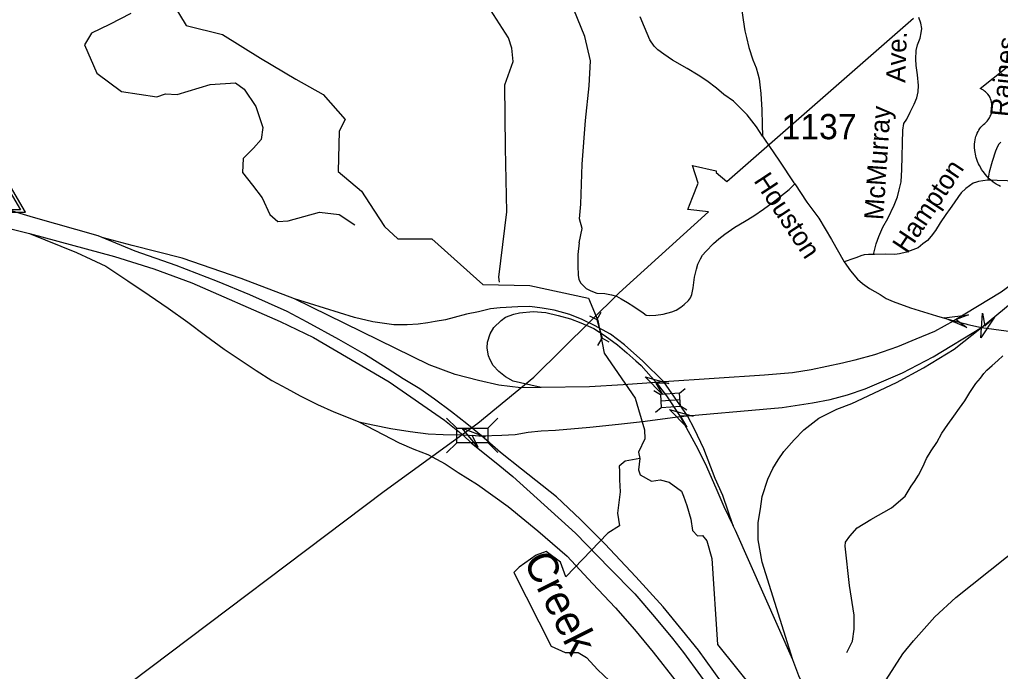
# Model space of a CAD drawing. Extents: x 990631 to 1056237, y 535999 to 585651.
# Drawn here: x 1039191 to 1044054, y 560525 to 563754 of the extents above; entities that cross this region are included whole.
import ezdxf

# ---------------------------------------------------------------- set-up
doc = ezdxf.new("R2010")
doc.units = 0
for name, color, linetype in [('Exist Boundary Political City Limit New', 7, 'Continuous'), ('Exist Hydrographic Creek Single Shore', 7, 'Continuous'), ('Exist Hydrographic Creek Single Shore Label', 7, 'Continuous'), ('Exist Road Non-System Type 51', 7, 'Continuous'), ('Exist Road Non-System Type 51 Label', 7, 'Continuous'), ('Exist Road Primary Interstate Divided Center Attributed', 7, 'Continuous'), ('Exist Road Primary Interstate Ramp 1 Lane Attributed', 7, 'Continuous'), ('Exist Road Primary Interstate Structure Standard Bridge CELL', 7, 'Continuous'), ('Exist Road Primary NC Attributed', 7, 'Continuous'), ('Exist Road Primary US Divided Attributed', 7, 'Continuous'), ('Exist Road Primary US Shield CELL', 7, 'Continuous'), ('Exist Road Secondary Structure Culvert CELL', 7, 'Continuous'), ('Exist Road Secondary Structure Standard Bridge Attributed CELL', 7, 'Continuous'), ('Exist Road Secondary Type 51 Attributed', 7, 'Continuous'), ('Exist Road Secondary Type 51 Label', 7, 'Continuous'), ('Exist Road Secondary Type 51 Number Label', 7, 'Continuous'), ('Exist Survey Geodetic Marker CELL', 7, 'Continuous')]:
    doc.layers.add(name, color=color, linetype=linetype)

msp = doc.modelspace()

# ---------------------------------------------------------------- linework, layer by layer
at = {"layer": 'Exist Boundary Political City Limit New'}
msp.add_lwpolyline([(1040073.9, 557988.5), (1039959.6, 558234.4), (1040030.1, 558256.9), (1039357.1, 559263.7), (1038967.6, 559887.1), (1039740.5, 560469.5), (1040999.5, 561417.5), (1041463.6, 561753.6), (1041741.1, 561981.8), (1042163.9, 562399.8), (1042607.6, 562801.8), (1042504.3, 562813.3), (1042528.4, 562873.1), (1042556.6, 562942.8), (1042527.6, 563031.9), (1042644.9, 563004.8), (1042645.8, 562995.9), (1042698.7, 562951.6), (1043624.2, 563761.7)], dxfattribs=at)
at = {"layer": 'Exist Hydrographic Creek Single Shore'}
for points in [[(1039816.1, 563950.7), (1039917.4, 563890.2), (1040017, 563724.5), (1040198.1, 563679.6), (1040385.2, 563562.6), (1040560.2, 563458.8), (1040697.1, 563383.2), (1040806.2, 563258.4), (1040776.4, 563201), (1040771.3, 563000.9), (1040886.3, 562903.4), (1040926.2, 562843.5), (1041000.9, 562729.6), (1041067.1, 562667.1), (1041234.8, 562667.1), (1041488.8, 562441.6), (1041720.9, 562435.8), (1042012.7, 562374.3), (1042058.8, 562262.9), (1042089.5, 562101.5), (1042243.1, 561878.7)], [(1041571.4, 562452.3), (1041567.3, 562478), (1041607.8, 562802.3), (1041601.2, 563118), (1041597.5, 563430.3), (1041638.7, 563546.9), (1041631.8, 563612.1), (1041614.6, 563663.6), (1041422.6, 563965.5)], [(1042243.1, 561878.7), (1042290.4, 561722)], [(1042290.4, 561722), (1042291.5, 561676), (1042260.1, 561610.8), (1042266.8, 561578.8), (1042193.8, 561565.3), (1042163.4, 561540.6), (1042165.7, 561515.8), (1042165.7, 561473.1), (1042169.1, 561413.6), (1042156.7, 561309.1), (1042165.7, 561245), (1042108.4, 561209.6), (1041899.4, 560992.8), (1041873.5, 561066.4), (1041802.7, 561119.2), (1041753.3, 561100.1), (1041667.9, 561041.6), (1041642.1, 561013.6), (1041826.3, 560648.9), (1041896, 560617.5), (1041960.1, 560617.5), (1042002.8, 560592.7), (1042058.9, 560532.1), (1042114, 560479.3)], [(1042266.8, 561578.8), (1042260.1, 561522.6), (1042269.1, 561499), (1042325.2, 561467.5), (1042367.9, 561474.3), (1042411.8, 561461.9), (1042473.6, 561418.1), (1042482.6, 561393.4), (1042500.5, 561346.2), (1042519.6, 561278.7), (1042528.6, 561222.6), (1042553.3, 561195.6), (1042576.9, 561197.8), (1042599.4, 561170.9), (1042624.3, 561083), (1042651, 560657.4), (1042834.2, 560432.1), (1042971.6, 560209.7), (1043109, 560049.3), (1043414.4, 560008), (1043506, 559824.7), (1043582.4, 559469.5), (1043607.2, 559178)]]:
    msp.add_lwpolyline(points, dxfattribs=at)
at = {"layer": 'Exist Road Non-System Type 51'}
for points in [[(1041965.5, 562647.8), (1041980.4, 562719.1), (1041966.7, 562767.1), (1041973.6, 562839.1), (1041980.4, 563038.2), (1041997.6, 563254.3), (1042014.7, 563425.9), (1042021.6, 563549.4), (1041994.1, 563669.5), (1041939.3, 563804.4), (1041874.1, 564003.4), (1041836.4, 564209.3), (1041819.2, 564384.3), (1041791.8, 564494.1), (1041748.5, 564614.1)], [(1039742.5, 563784.2), (1039637.3, 563729.6), (1039547.6, 563686.7), (1039512.5, 563628.2), (1039574.9, 563487.8), (1039695.7, 563398.1), (1039871.1, 563370.8), (1039914, 563386.4), (1039972.5, 563382.5), (1040136.2, 563433.2), (1040261, 563441), (1040303.9, 563409.8), (1040362.3, 563324), (1040397.4, 563218.7), (1040389.6, 563160.2), (1040350.6, 563117.3), (1040300, 563066.5), (1040296.1, 562996.3), (1040346.7, 562933.9), (1040393.5, 562871.5), (1040432.5, 562788.1), (1040471.5, 562753), (1040522.1, 562756.9), (1040678.1, 562799.8), (1040775.5, 562788.1), (1040853.5, 562737.4)], [(1043424.6, 562590.8), (1043438.3, 562642.6), (1043451.6, 562680.1), (1043470.9, 562725.5), (1043496.4, 562768.6), (1043528.5, 562833.8), (1043543.8, 562875.3), (1043553.1, 562911), (1043562.3, 562950.8), (1043566.3, 563010.7), (1043570.5, 563206.7), (1043575.5, 563238.4), (1043590.1, 563260.1), (1043607.5, 563295.6), (1043626.7, 563335), (1043639.7, 563366.6), (1043646.7, 563396.3), (1043647.7, 563428.3), (1043643.4, 563480.6), (1043636.7, 563526.7), (1043635.8, 563558.7), (1043637.2, 563600.7), (1043644.2, 563628.6), (1043657.2, 563662.1), (1043662, 563688.1), (1043664.8, 563710), (1043659.5, 563736.1), (1043650.5, 563764.5)], [(1044056.8, 563147.1), (1044046.6, 563137.3), (1044040.2, 563125.4), (1044029.5, 563101.9), (1044013.9, 563050.3), (1043998.2, 562998.8), (1043992.8, 562958.9)], [(1041965.5, 562647.8), (1041959.7, 562589.9), (1041960, 562535.8), (1041960.4, 562485.8), (1041963.9, 562467.7), (1041973.1, 562449.3), (1042000.4, 562422.4), (1042023.9, 562409.7), (1042053.7, 562398.7), (1042093.7, 562397.5), (1042125.4, 562390.4), (1042151.2, 562383.5), (1042174.8, 562370.8), (1042206.2, 562351.8), (1042237.6, 562332.8), (1042282.6, 562301.3), (1042298.2, 562288.7), (1042316.2, 562288.2), (1042346.4, 562289.2), (1042382.5, 562294), (1042425, 562306.8), (1042447.1, 562314), (1042469.6, 562329.3), (1042486.1, 562342.8), (1042508.7, 562362.1), (1042517.2, 562375.8), (1042523.7, 562391.6), (1042530.8, 562425.5), (1042538.4, 562477.2), (1042547.6, 562517), (1042554.6, 562542.7), (1042567.5, 562568.4), (1042578, 562586), (1042594.6, 562605.5), (1042631.8, 562644.4), (1042658.7, 562667.4), (1042687.4, 562690.7), (1042738.5, 562725.1), (1042785.5, 562753.5), (1042832.5, 562782), (1042879.5, 562814.5), (1042936.8, 562856.7), (1042984.2, 562893.2), (1043006.8, 562912.5), (1043035.5, 562939.6)], [(1043992.8, 562958.9), (1043966.7, 562955.9), (1043946.7, 562952.5), (1043936.4, 562948.7), (1043920.3, 562943.2), (1043901.8, 562929.8), (1043883.3, 562916.3), (1043860.7, 562895.2), (1043846.1, 562877.7), (1043825.1, 562846.3), (1043806.1, 562818.8), (1043783.3, 562787.5), (1043755.9, 562746.4), (1043732.7, 562709.1), (1043711.7, 562681.7), (1043693.1, 562660.2), (1043670.6, 562643.1), (1043646, 562623.8), (1043619.5, 562612.7), (1043589.1, 562601.7), (1043554.9, 562592.8), (1043530.6, 562589.5), (1043482.6, 562591.1), (1043430.6, 562590.7), (1043424.6, 562590.8)], [(1044144.6, 562946.1), (1044128.7, 562950.6), (1044088.8, 562955.8), (1044038.8, 562957.4), (1043992.8, 562958.9)], [(1043424.6, 562590.8), (1043400.6, 562589.7), (1043378.6, 562588.3), (1043362.4, 562582.9), (1043342.1, 562575.5), (1043328, 562570), (1043279.2, 562553.8)], [(1043293.3, 560618.8), (1043321, 560673.9), (1043329, 560733.7), (1043329.2, 560803.8), (1043305.9, 560950.7), (1043284.1, 561145.6), (1043286.9, 561165.3), (1043307.7, 561194.7), (1043345.1, 561235.6), (1043412.6, 561277.5), (1043514.3, 561334.2), (1043582.5, 561392.7), (1043612, 561442), (1043628.7, 561465.5), (1043647.7, 561496.9), (1043669.1, 561538.3), (1043688.4, 561579.7), (1043711.5, 561617.1), (1043739, 561658.1), (1043764.5, 561705.4), (1043793.8, 561748.5), (1043823.2, 561789.5), (1043852.4, 561828.7), (1043877.8, 561865.8), (1043903, 561907.1), (1043932.5, 561950.2), (1043955.3, 561977.5), (1043972.1, 562001), (1043986.7, 562016.5), (1044013.3, 562039.6), (1044042.3, 562064.8), (1044066.9, 562087.9)]]:
    msp.add_lwpolyline(points, dxfattribs=at)
at = {"layer": 'Exist Road Primary Interstate Divided Center Attributed'}
for points in [[(1039600.5, 562674), (1039581.5, 562681.8), (1039260.3, 562773.6), (1039105.6, 562819.5), (1038966.3, 562855.2), (1038859.2, 562880.8), (1038745.4, 562902.9), (1038645.1, 562914.8), (1038408, 562926.1), (1038149.5, 562961), (1037990.1, 562982.4), (1037802.6, 563003.9), (1037599, 563028), (1037373.9, 563046.7), (1037155.6, 563058.8), (1036983.1, 563069), (1036964, 563070.2), (1036848.9, 563077.1), (1036652.4, 563089.6)], [(1036616.9, 563035.1), (1037143.5, 563005.2), (1037360.5, 562986.4), (1037616.4, 562958.3), (1037911.1, 562923.5), (1038670.6, 562818.9), (1038820.6, 562792.1), (1039040.2, 562743.9), (1039239.7, 562694.9)], [(1039239.7, 562694.9), (1039661.8, 562580.4), (1039857.3, 562518.8), (1040044.9, 562449.1), (1040482.9, 562258.8), (1040649, 562178.4), (1041024, 561958.6), (1041297.3, 561769.7), (1041388.8, 561695.9)], [(1041481.9, 561691.2), (1041408.5, 561750.9), (1041332.1, 561811.2), (1041249.1, 561872.8), (1041175.4, 561923.8), (1041092.3, 561974.7), (1041013.3, 562025.6), (1040900.8, 562096.6), (1040774.9, 562169), (1040616.8, 562254.8), (1040517.7, 562307), (1040332.9, 562390.1), (1040172.1, 562455.8), (1039967.2, 562534.8), (1039763.6, 562607.2), (1039600.5, 562674)], [(1041388.8, 561695.9), (1041431.2, 561655.8), (1041554.5, 561557.9), (1041637.5, 561490.9), (1041947.6, 561209.1), (1042116.3, 561036.3), (1042242.3, 560909), (1042340, 560795.1), (1042428.4, 560687.9), (1042483.4, 560618.2), (1042567.4, 560501.8), (1042624, 560426.5), (1042753.9, 560241.6), (1042851.7, 560083.5), (1042956.2, 559903.9), (1043013.8, 559788.7), (1043055.1, 559700.3)], [(1043093.8, 559748.6), (1043070.1, 559808.8), (1043011.1, 559932.1), (1042940.1, 560064.7), (1042859.8, 560201.4), (1042788.8, 560308.6), (1042672.2, 560470.8), (1042557, 560628.9), (1042478, 560726.7), (1042381.6, 560844.6), (1042246.3, 560993.4), (1042093.6, 561156.9), (1041973, 561277.5), (1041853.8, 561388.7), (1041679.7, 561526.7), (1041575.2, 561608.5), (1041481.9, 561691.2)]]:
    msp.add_lwpolyline(points, dxfattribs=at)
at = {"layer": 'Exist Road Primary Interstate Ramp 1 Lane Attributed'}
msp.add_line((1042502.4, 561790.8), (1042385.5, 561959.5), dxfattribs=at)
for points in [[(1042385.5, 561959.5), (1042281.1, 562061.8), (1042190.4, 562141.8), (1042121.3, 562195.6), (1042041.7, 562239.1), (1041980.2, 562268.3), (1041919.1, 562292), (1041842.3, 562313.5), (1041782.3, 562324.3), (1041721.6, 562332), (1041661.6, 562331.3), (1041574.2, 562325.4), (1041526.4, 562320.8), (1041467, 562305.6), (1041407.5, 562293.9), (1041345.8, 562277.6), (1041303.8, 562267.1), (1041251.4, 562257.8), (1041215.2, 562250.8), (1041168.2, 562244.8), (1041112.2, 562241.3), (1041047, 562242.4), (1040943.2, 562256.4), (1040851.2, 562277.4), (1040553.6, 562370.6)], [(1041777.4, 561931.4), (1041674.4, 561953.4), (1041638.3, 561962.7), (1041601, 561983.7), (1041566.9, 562009.9), (1041539.7, 562040.9), (1041524.6, 562067.4), (1041515.9, 562087.5), (1041512.4, 562106.1), (1041509.5, 562127.7), (1041511.8, 562155.7), (1041524.1, 562197.1), (1041543.4, 562228.5), (1041578.8, 562263.6), (1041601.1, 562279.2), (1041641.8, 562293.9), (1041669.7, 562300.9), (1041737.3, 562307.9)], [(1041737.3, 562307.9), (1041800.3, 562302.1), (1041862, 562288.1), (1041922.6, 562270.6), (1041973.9, 562251.9), (1042039.2, 562222.8), (1042094, 562186.6), (1042155.7, 562142.3), (1042202.3, 562102.6), (1042246.2, 562063.1), (1042273, 562039.8), (1042347.7, 561956.3)], [(1043024.5, 560581.4), (1042872.6, 561066.4), (1042853.8, 561176.4), (1042853.8, 561262.3), (1042864.5, 561329.4), (1042872.6, 561391.1), (1042900.6, 561476.9), (1042926.4, 561530.2), (1042951.8, 561573.3), (1042979.9, 561613.5), (1043031.3, 561671.6), (1043080.4, 561720.8), (1043154.1, 561778.8), (1043243.4, 561823.5), (1043317.1, 561852.6), (1043538.8, 561956.6), (1043673.6, 562028.8), (1043824.8, 562120.9), (1043960.7, 562229.1)], [(1042347.7, 561956.3), (1042398.3, 561889.3), (1042467.3, 561787.5)], [(1040873.9, 561761.5), (1041072.6, 561656.1), (1041145.2, 561625.1), (1041215.5, 561599.1), (1041302.1, 561552.3), (1041366.6, 561510.2), (1041460.9, 561450.3), (1041614.4, 561342), (1041760.4, 561221), (1041906.5, 561095), (1042032, 560959.6), (1042146.6, 560839.4), (1042241, 560732.6), (1042332, 560620.3), (1042446.6, 560474.2), (1042533.1, 560341.6), (1042616.6, 560213.2), (1042687.2, 560057), (1042750.1, 559900.7), (1042881, 559530.3)], [(1042467.3, 561787.5), (1042554.5, 561627.5), (1042596.9, 561540.2), (1042649.1, 561422), (1042683.8, 561341), (1042729.6, 561245.3)], [(1042729.6, 561245.3), (1042677.6, 561396.5), (1042640.7, 561480.9), (1042583.6, 561626.7), (1042537, 561724.7), (1042502.4, 561790.8)], [(1043024.5, 560581.4), (1042740.3, 561223), (1042729.6, 561245.3)], [(1043264.1, 560006.8), (1043179.8, 560188.8), (1043099.4, 560404.7), (1043055.5, 560502.4), (1043024.5, 560581.4)]]:
    msp.add_lwpolyline(points, dxfattribs=at)
at = {"layer": 'Exist Road Primary Interstate Structure Standard Bridge CELL'}
for p, q in [((1042336.2, 561915.5), (1042368.4, 561895.8)), ((1042463.1, 561902.3), (1042492.1, 561926.3)), ((1042370.6, 561864.3), (1042465.3, 561871)), ((1042343.8, 561808.7), (1042372.8, 561832.7)), ((1042467.5, 561840), (1042499.6, 561820.3)), ((1041308.8, 561779.1), (1041358.4, 561729.5)), ((1041512.3, 561729.1), (1041562, 561778.8)), ((1041308.8, 561607.9), (1041358.4, 561657.6)), ((1041512.3, 561658.9), (1041562, 561609.2))]:
    msp.add_line(p, q, dxfattribs=at)
for points in [[(1042372.8, 561832.7), (1042467.5, 561839.4), (1042463.1, 561902.5), (1042368.4, 561895.8)], [(1041358.4, 561729.5), (1041512.3, 561729.5), (1041512.3, 561657.6), (1041358.4, 561657.6)]]:
    msp.add_lwpolyline(points, close=True, dxfattribs=at)
at = {"layer": 'Exist Road Primary NC Attributed'}
msp.add_lwpolyline([(1043264.1, 560006.8), (1043301.1, 560087.7), (1043356.2, 560202.3), (1043396.6, 560300.1), (1043465.9, 560437.4), (1043488.5, 560482.8), (1043571.2, 560612), (1043623.3, 560676.2), (1043729.6, 560794.1), (1043834.2, 560890.3), (1044336.7, 561290.9), (1044875.9, 561701)], dxfattribs=at)
at = {"layer": 'Exist Road Primary US Divided Attributed'}
for points in [[(1045749.4, 563870.6), (1045521.5, 563680.7), (1045342.9, 563519.8), (1045208.9, 563394.6), (1044818, 563039.3), (1044797.9, 563023.6), (1044322.5, 562611.4), (1044182.1, 562494), (1044059, 562403.5), (1043823.6, 562261.7)], [(1043960.7, 562229.1), (1044274.8, 562488.4), (1044585.7, 562757.7), (1044907.3, 563037.1), (1045271.4, 563341), (1045289.3, 563358.9), (1045548.3, 563582.4), (1045803, 563790.2)], [(1039239.7, 562694.9), (1039473, 562600.2), (1039544.1, 562567.3), (1039618.4, 562532.9), (1039679, 562492.8), (1039728.1, 562459.2), (1039833.7, 562387.9), (1039927.9, 562324.8), (1040025.7, 562255.6), (1040113.6, 562188.8), (1040205.5, 562121.7), (1040289.8, 562065), (1040364.2, 562014.5), (1040442.7, 561966.1), (1040515.5, 561925.6), (1040582.4, 561889.5), (1040668.9, 561846.7), (1040749.8, 561810.1), (1040795.3, 561792.6), (1040873.9, 561761.5)], [(1040553.6, 562370.6), (1040290.2, 562470.9), (1039997.8, 562571.3), (1039749.7, 562634.2), (1039600.5, 562674)], [(1041777.4, 561931.4), (1041676.7, 561930), (1041568.1, 561942.1), (1041466.2, 561965.9), (1041350.6, 561994.8), (1041221.4, 562044.1), (1040553.6, 562370.6)], [(1043823.6, 562261.7), (1043727.3, 562209.1), (1043634.6, 562170.4), (1043544.4, 562132.7), (1043430.9, 562093.7), (1043332, 562066.1), (1043270.8, 562052.1), (1043116.3, 562018.1), (1043024.2, 562004.1), (1042884.8, 561991.7), (1042385.5, 561959.5)], [(1042502.4, 561790.8), (1042877.5, 561823.7), (1042973, 561832.7), (1043122.8, 561854.8), (1043209.6, 561871.7), (1043297, 561895.1), (1043383.7, 561924.6), (1043442.2, 561948.7), (1043569.7, 562003.2), (1043720.8, 562083.6), (1043960.7, 562229.1)], [(1042347.7, 561956.3), (1042183.7, 561944), (1042016.5, 561934.8), (1041777.4, 561931.4)], [(1042385.5, 561959.5), (1042347.7, 561956.3)], [(1040873.9, 561761.5), (1040942, 561745.8), (1041031.4, 561728.4), (1041127, 561713.4), (1041217, 561701.8), (1041290.7, 561698.4), (1041388.8, 561695.9)], [(1041481.9, 561691.2), (1041582.6, 561695.5), (1041648.8, 561698.9), (1041713.4, 561709.1), (1041778, 561715.9), (1041847.7, 561719.3), (1042019.3, 561734.6), (1042160.4, 561749.9), (1042279.3, 561761.8), (1042467.3, 561787.5)], [(1042467.3, 561787.5), (1042502.4, 561790.8)], [(1041388.8, 561695.9), (1041481.9, 561691.2)]]:
    msp.add_lwpolyline(points, dxfattribs=at)
at = {"layer": 'Exist Road Primary US Shield CELL'}
msp.add_lwpolyline([(1044055.2, 562927.1), (1044047.1, 562931.2), (1044034.2, 562938.6), (1044019.2, 562949), (1044007.8, 562958.2), (1043999.5, 562965.7), (1043987.3, 562978.2), (1043980.1, 562986.3), (1043968.8, 563000.9), (1043961.6, 563011.5), (1043956.9, 563019.2), (1043950.1, 563031.7), (1043946.4, 563039.5), (1043941.5, 563050.9), (1043937.7, 563061.3), (1043934.5, 563071.2), (1043932.8, 563077.5), (1043930.3, 563088.5), (1043928.8, 563096.3), (1043927.4, 563107.1), (1043926.6, 563118.4), (1043926.5, 563128.8), (1043926.7, 563137.5), (1043927.7, 563147.6), (1043929.4, 563158.3), (1043931.5, 563167.5), (1043933.3, 563174.1), (1043936.1, 563182.1), (1043939.7, 563191), (1043943.9, 563199.5), (1043948, 563206.6), (1043953.1, 563214.2), (1043958.1, 563220.7), (1043964.7, 563227.8), (1043971.5, 563234.3), (1043977.8, 563239.4), (1043985.2, 563246.7), (1043989.1, 563251.1), (1043993.7, 563257.3), (1043997.5, 563263), (1044000.4, 563268.1), (1044004.3, 563275.6), (1044006.7, 563281.2), (1044009.7, 563289.9), (1044011.1, 563296), (1044012.7, 563303.8), (1044013.6, 563311.2), (1044014, 563320.4), (1044013.8, 563328), (1044012.8, 563336.8), (1044011.1, 563345.4), (1044009.1, 563352.8), (1044005.9, 563361.3), (1044003, 563367.5), (1043998.1, 563376), (1043992.6, 563383.8), (1043986.9, 563390.2), (1043981.3, 563395.9), (1043975.8, 563400.1), (1043970.6, 563403.9), (1043964.1, 563407.8), (1043957.7, 563410.9), (1043953.8, 563412.5), (1044082.4, 563515)], dxfattribs=at)
at = {"layer": 'Exist Road Secondary Structure Culvert CELL'}
for p, q in [((1042017.1, 562287), (1042053, 562268)), ((1042073.9, 562302.9), (1042053, 562268)), ((1042053, 562268), (1042079.1, 562174.9)), ((1042058.2, 562140), (1042079.1, 562174.9)), ((1042115, 562155.9), (1042079.1, 562174.9))]:
    msp.add_line(p, q, dxfattribs=at)
at = {"layer": 'Exist Road Secondary Structure Standard Bridge Attributed CELL'}
for points in [[(1043887.9, 562229), (1043775.3, 562275.9), (1043896.2, 562291.6), (1043835.7, 562267.8)], [(1044025.2, 562279.8), (1043958.2, 562177.9), (1043965.3, 562299.6), (1043977.4, 562235.8)], [(1042378.8, 561897.1), (1042293.4, 561984.2), (1042410.9, 561951.5), (1042345.9, 561953.2)], [(1042499.6, 561735), (1042414.2, 561822), (1042531.7, 561789.3), (1042466.7, 561791)], [(1041463, 561634.7), (1041385.9, 561729.1), (1041499.9, 561685.9), (1041435.4, 561693.5)]]:
    msp.add_lwpolyline(points, close=True, dxfattribs=at)
at = {"layer": 'Exist Road Secondary Type 51 Attributed'}
for points in [[(1042772.9, 563798.6), (1042779.6, 563752.4), (1042787.7, 563698), (1042794.8, 563665.9), (1042807, 563615.4), (1042827.2, 563554.8), (1042844, 563514.2), (1042851, 563485.9), (1042858.1, 563459.7), (1042861.3, 563431.5), (1042865.9, 563387.3), (1042871.2, 563307.2), (1042873, 563234.9), (1042875, 563176.9)], [(1042875, 563176.9), (1042844.5, 563221.9), (1042798.3, 563281.5), (1042765.4, 563314.5), (1042730.6, 563349.7), (1042683.5, 563383.2), (1042646.5, 563414.4), (1042599.6, 563449.9), (1042556.6, 563479.4), (1042501.6, 563511.1), (1042428.8, 563553.6), (1042385.8, 563582.9), (1042356.4, 563603.9), (1042337, 563622.5), (1042316, 563653.1), (1042289.9, 563716.9), (1042268.2, 563768.5)], [(1042875, 563176.9), (1042888.5, 563156.3), (1042905.7, 563129.8), (1042959.1, 563052.1), (1043029.8, 562945.9), (1043035.5, 562939.6), (1043094.7, 562849.7), (1043154.3, 562769.7), (1043217.4, 562663.9), (1043279.2, 562553.8), (1043311.3, 562509.4), (1043346.1, 562468.7), (1043371.4, 562447.1), (1043405.1, 562422.3), (1043457.9, 562391.4), (1043488.2, 562372.9), (1043523.6, 562357.2), (1043609, 562326), (1043737.1, 562286.4), (1043823.6, 562261.7)], [(1043823.6, 562261.7), (1043883.8, 562245.9), (1043892.6, 562244)], [(1043892.6, 562244), (1043960.7, 562229.1)], [(1043960.7, 562229.1), (1044083.2, 562211.1), (1044174.8, 562205.5), (1044268.6, 562199.3), (1044337.7, 562197.6), (1044385.5, 562188.1), (1044417.5, 562179.6), (1044439.4, 562167.8), (1044464.1, 562153.8), (1044490, 562138.6), (1044507.5, 562125.6), (1044525.8, 562103.3), (1044552.8, 562072.3), (1044610.7, 562010.6), (1044875.9, 561701)]]:
    msp.add_lwpolyline(points, dxfattribs=at)
at = {"layer": 'Exist Survey Geodetic Marker CELL'}
for points in [[(1039221, 562800), (1039087, 563026.1), (1038953.6, 562800)], [(1039195.1, 562812.2), (1038979.5, 562812.2), (1039087, 562994.3)]]:
    msp.add_lwpolyline(points, close=True, dxfattribs=at)

# ---------------------------------------------------------------- texts
at = {"layer": 'Exist Hydrographic Creek Single Shore Label'}
msp.add_text('Creek', height=150, rotation=296.5609, dxfattribs=at).set_placement((1041687, 561072.7))
at = {"layer": 'Exist Road Non-System Type 51 Label'}
for s, rotation, p in [('Ave.', 88.0298, (1043582.4, 563440.4)), ('Raines', 84.298, (1044097.4, 563269.5)), ('McMurray', 86.1767, (1043473.1, 562759.1)), ('Hampton', 56.254, (1043591.9, 562589.5))]:
    msp.add_text(s, height=95, rotation=rotation, dxfattribs=at).set_placement(p)
at = {"layer": 'Exist Road Secondary Type 51 Label'}
msp.add_text('Houston', height=95, rotation=303.3934, dxfattribs=at).set_placement((1042828.6, 562955.7))
at = {"layer": 'Exist Road Secondary Type 51 Number Label'}
msp.add_text('1137', height=125, dxfattribs=at).set_placement((1042969.3, 563161.2))

doc.saveas('drawing.dxf')
